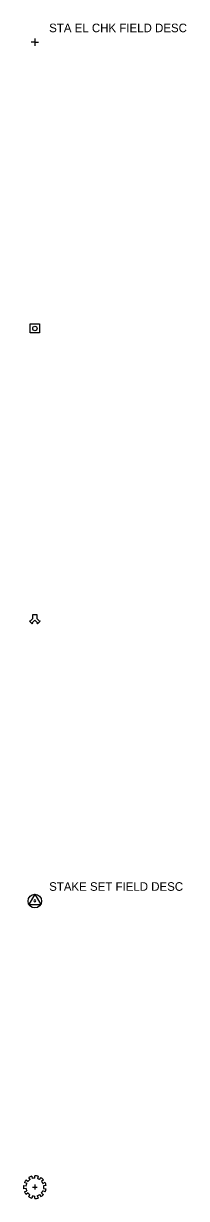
# Model space of a CAD drawing. Extents: x 98 to 2902, y -6 to 903.
# Drawn here: x 2098 to 2126.5, y 698 to 903.3 of the extents above; entities that cross this region are included whole.
import ezdxf

# ---------------------------------------------------------------- set-up
doc = ezdxf.new("R2010")
doc.units = 0
for name, color, linetype in [('V-HTCW-DEVC', 7, 'Continuous'), ('V-SITE-VEGE', 7, 'Continuous'), ('V-SURV-DATA', 7, 'Continuous'), ('V-WATR-DEVC', 7, 'Continuous')]:
    doc.layers.add(name, color=color, linetype=linetype)

msp = doc.modelspace()

# ---------------------------------------------------------------- linework, layer by layer
at = {"layer": 'V-HTCW-DEVC'}
msp.add_lwpolyline([(2099.21, 849.24), (2099.21, 850.83), (2100.79, 850.83), (2100.79, 849.24)], close=True, dxfattribs=at)
msp.add_ellipse((2100, 850), major_axis=(0, 0.396), ratio=0.957579, dxfattribs=at)
at = {"layer": 'V-SITE-VEGE'}
for p, q in [((2098.03, 700.25), (2098.46, 700.18)), ((2098.58, 700.61), (2098.19, 700.78)), ((2098.49, 701.26), (2098.81, 700.98)), ((2099.17, 701.3), (2098.93, 701.65)), ((2099.46, 701.89), (2099.56, 701.47)), ((2099.58, 700), (2100.42, 700)), ((2100, 701.53), (2100.01, 701.96)), ((2100, 700.42), (2100, 699.58)), ((2100.57, 701.88), (2100.45, 701.47)), ((2100.84, 701.29), (2101.08, 701.64)), ((2101.51, 701.27), (2101.19, 700.99)), ((2101.42, 700.62), (2101.8, 700.82)), ((2101.97, 700.25), (2101.54, 700.19)), ((2098.46, 699.76), (2098.04, 699.69)), ((2098.19, 699.16), (2098.58, 699.35)), ((2098.83, 698.96), (2098.5, 698.68)), ((2098.94, 698.3), (2099.15, 698.68)), ((2099.58, 698.48), (2099.46, 698.07)), ((2100, 697.99), (2100, 698.42)), ((2100.43, 698.49), (2100.56, 698.08)), ((2101.08, 698.31), (2100.85, 698.68)), ((2101.17, 698.95), (2101.5, 698.68)), ((2101.81, 699.15), (2101.41, 699.31)), ((2101.54, 699.75), (2101.97, 699.7))]:
    msp.add_line(p, q, dxfattribs=at)
for radius, start, end in [(1.98, 172.27, 188.583), (1.98, 139.7777, 156.0738), (1.56, 156.0557, 172.7558), (1.56, 122.254, 140.086), (1.98, 105.972, 122.5562), (1.56, 89.9461, 106.3473), (1.98, 73.2952, 89.5718), (1.56, 57.451, 73.0843), (1.98, 40.7122, 57.1166), (1.56, 24.4529, 40.4774), (1.56, 351.5431, 7.6203), (1.98, 7.9671, 24.8625), (1.98, 204.5394, 220.9852), (1.56, 188.0619, 204.0332), (1.56, 221.2062, 236.7795), (1.98, 237.6108, 254.1981), (1.56, 254.31, 270.043), (1.98, 270.0356, 286.342), (1.56, 285.9559, 303.0564), (1.98, 302.8434, 319.0222), (1.56, 318.6432, 334.5795), (1.98, 335.3123, 351.7042)]:
    msp.add_arc((2100, 699.98), radius, start, end, dxfattribs=at)
at = {"layer": 'V-SURV-DATA'}
for p, q in [((2100, 900), (2099.35, 900)), ((2100, 900.65), (2100, 899.35)), ((2100, 900), (2100.65, 900)), ((2100, 751.14), (2098.97, 749.35)), ((2098.97, 749.35), (2101.03, 749.35)), ((2100, 751.14), (2101.03, 749.35))]:
    msp.add_line(p, q, dxfattribs=at)
msp.add_circle((2100, 749.95), 1.19, dxfattribs=at)
msp.add_arc((2100, 750), 0.165, 92.2877, 90.5674, dxfattribs=at)
at = {"layer": 'V-WATR-DEVC'}
for points in [[(2100, 799.01), (2099.53, 798.54), (2099.6, 798.46), (2099.53, 798.39), (2099.05, 798.87), (2099.13, 798.94), (2099.2, 798.87), (2099.67, 799.34), (2099.67, 800), (2100.33, 800), (2100.33, 799.34)], [(2100.33, 799.34), (2100.8, 798.87), (2100.87, 798.94), (2100.95, 798.87), (2100.47, 798.39), (2100.4, 798.46), (2100.47, 798.54), (2100, 799.01)]]:
    msp.add_lwpolyline(points, dxfattribs=at)

# ---------------------------------------------------------------- texts
at = {"layer": 'V-SURV-DATA'}
for s, p in [('STA EL CHK FIELD DESC', (2102.5, 901.75)), ('STAKE SET FIELD DESC', (2102.5, 751.75))]:
    msp.add_text(s, height=1.5, dxfattribs=at).set_placement(p)

doc.saveas('drawing.dxf')
